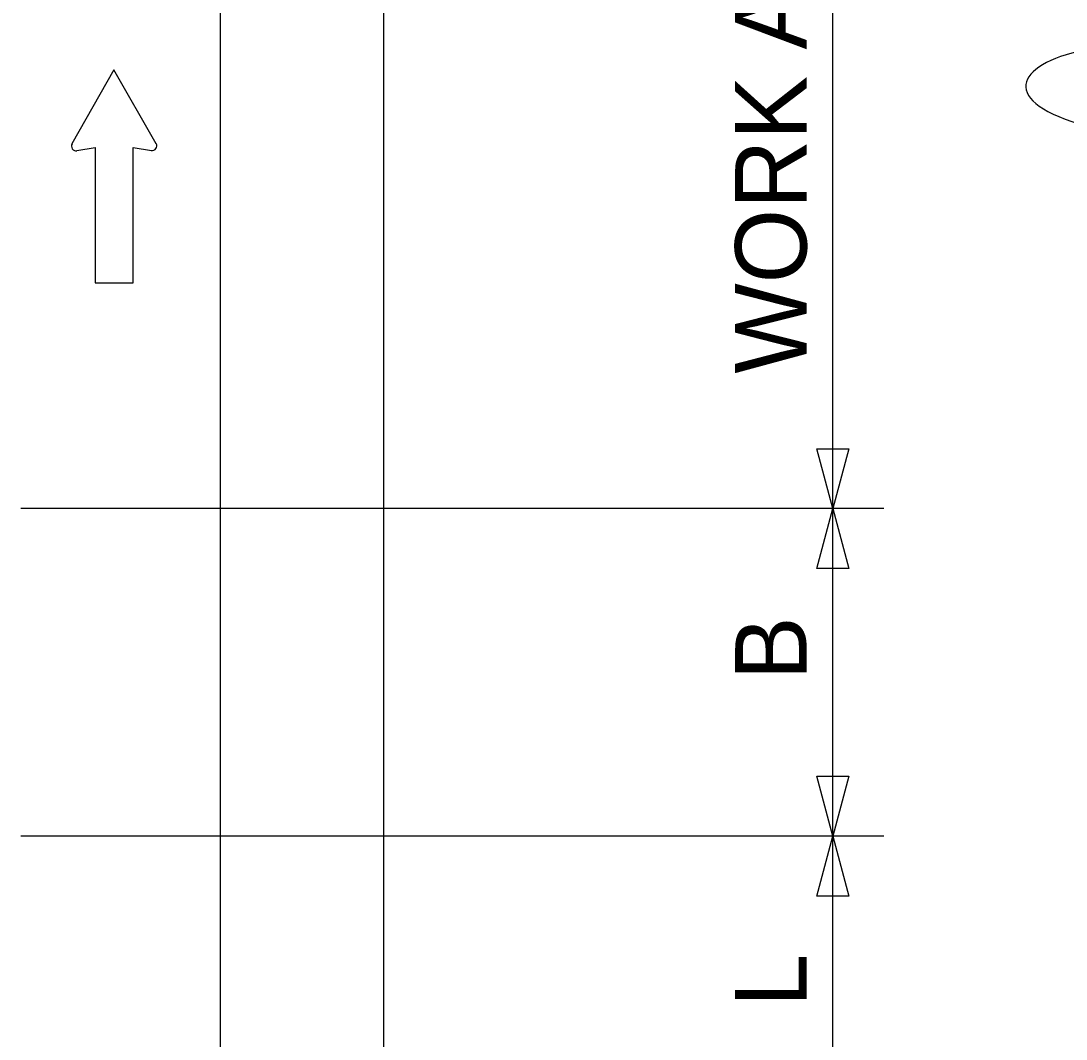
# Model space of a CAD drawing. Extents: x 16732 to 18475, y 5726 to 6929.
# Drawn here: x 17125.9 to 17228.2, y 6530.1 to 6629.8 of the extents above; entities that cross this region are included whole.
import ezdxf

# ---------------------------------------------------------------- set-up
doc = ezdxf.new("R2010")
doc.units = 0
for name, color, linetype in [('MT_SCRATCH_LEVEL_E', 7, 'Continuous'), ('PAVT_EDGE_EX', 7, 'Continuous'), ('TYPICAL_TEXT_DIMEN_PR', 7, 'Continuous')]:
    doc.layers.add(name, color=color, linetype=linetype)

msp = doc.modelspace()

# ---------------------------------------------------------------- linework, layer by layer
at = {"layer": 'MT_SCRATCH_LEVEL_E'}
for p, q in [((17134.97, 6624.98), (17130.86, 6617.74)), ((17134.97, 6624.98), (17130.86, 6617.74)), ((17139.12, 6617.74), (17134.97, 6624.98)), ((17139.12, 6617.74), (17134.97, 6624.98)), ((17131.34, 6617.06), (17133.12, 6617.37)), ((17131.34, 6617.06), (17133.12, 6617.37)), ((17133.12, 6617.37), (17133.12, 6604.11)), ((17133.12, 6617.37), (17133.12, 6604.11)), ((17136.86, 6604.11), (17136.86, 6617.37)), ((17136.86, 6617.37), (17138.64, 6617.06)), ((17136.86, 6604.11), (17136.86, 6617.37)), ((17136.86, 6617.37), (17138.64, 6617.06)), ((17133.12, 6604.11), (17136.86, 6604.11)), ((17133.12, 6604.11), (17136.86, 6604.11))]:
    msp.add_line(p, q, dxfattribs=at)
for centre, start, end in [((17131.27, 6617.51), 150.4248, 279.9638), ((17131.27, 6617.51), 150.4248, 279.9638), ((17138.71, 6617.52), 260.0362, 29.7731), ((17138.71, 6617.52), 260.0362, 29.7731)]:
    msp.add_arc(centre, 0.463, start, end, dxfattribs=at)
at = {"layer": 'PAVT_EDGE_EX'}
for p, q in [((17145.36, 6924.76), (17145.36, 6059.7)), ((17161.36, 6924.76), (17161.36, 6059.7))]:
    msp.add_line(p, q, dxfattribs=at)
at = {"layer": 'TYPICAL_TEXT_DIMEN_PR'}
for p, q in [((17205.36, 6582.03), (17205.36, 6695.75)), ((17205.36, 6582.03), (17203.79, 6587.89)), ((17203.79, 6587.89), (17205.36, 6587.89)), ((17205.36, 6587.89), (17206.93, 6587.89)), ((17206.93, 6587.89), (17205.36, 6582.03)), ((17210.36, 6582.03), (17125.86, 6582.03)), ((17203.79, 6576.16), (17205.36, 6582.03)), ((17205.36, 6549.97), (17205.36, 6582.03)), ((17205.36, 6582.03), (17206.93, 6576.16)), ((17205.36, 6576.16), (17203.79, 6576.16)), ((17206.93, 6576.16), (17205.36, 6576.16)), ((17205.36, 6549.97), (17203.79, 6555.83)), ((17203.79, 6555.83), (17205.36, 6555.83)), ((17205.36, 6555.83), (17206.93, 6555.83)), ((17206.93, 6555.83), (17205.36, 6549.97)), ((17210.36, 6549.97), (17125.86, 6549.97)), ((17203.79, 6544.1), (17205.36, 6549.97)), ((17205.36, 6549.97), (17206.93, 6544.1)), ((17205.36, 6519.39), (17205.36, 6549.97)), ((17205.36, 6544.1), (17203.79, 6544.1)), ((17206.93, 6544.1), (17205.36, 6544.1))]:
    msp.add_line(p, q, dxfattribs=at)
msp.add_open_spline([(17208.74, 6636.6), (17257.65, 6638.89), (17257.65, 6628.28), (17222.32, 6628.28), (17222.32, 6617.27), (17265.17, 6616.02), (17276.52, 6616.04)], degree=3, dxfattribs=at)

# ---------------------------------------------------------------- texts
for s, p in [('WORK AREA VARIES', (17202.8, 6595.24)), ('B', (17202.8, 6565.23)), ('L', (17202.8, 6533.26))]:
    msp.add_text(s, height=7, rotation=90, dxfattribs=at).set_placement(p)

doc.saveas('drawing.dxf')
